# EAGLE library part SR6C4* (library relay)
Safety Relay SR6 SCHRACK sensitive 6 pole 8 A Source: http://www.schrack.com/.. 6688.pdf
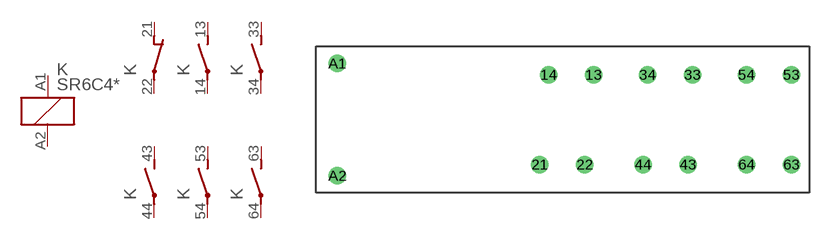
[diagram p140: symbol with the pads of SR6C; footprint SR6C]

Designator prefix K; gates 1=K 2=O 3=S 4=S 5=S 6=S 7=S

## SR6C4S05 (OC_FARNELL: unknown; OC_NEWARK: unknown), SR6C4S06 (OC_FARNELL: unknown; OC_NEWARK: unknown), SR6C4S09 (OC_FARNELL: unknown; OC_NEWARK: unknown), SR6C4S12 (OC_FARNELL: unknown; OC_NEWARK: unknown), SR6C4S15 (OC_FARNELL: unknown; OC_NEWARK: unknown), SR6C4S18 (OC_FARNELL: unknown; OC_NEWARK: unknown), SR6C4S21 (OC_FARNELL: unknown; OC_NEWARK: unknown), SR6C4S24 (OC_FARNELL: unknown; OC_NEWARK: unknown), SR6C4S36 (OC_FARNELL: unknown; OC_NEWARK: unknown), SR6C4S40 (OC_FARNELL: unknown; OC_NEWARK: unknown), SR6C4S48 (OC_FARNELL: unknown; OC_NEWARK: unknown)  [SR6C]
13  3:S  pas
14  3:P  pas
21  2:O  pas
22  2:P  pas
33  4:S  pas
34  4:P  pas
43  5:S  pas
44  5:P  pas
53  6:S  pas
54  6:P  pas
63  7:S  pas
64  7:P  pas
A1  1:1  pas
A2  1:2  pas

## Footprint SR6C (pad centres in mm)
Safety Relay SR6 SCHRACK sensitive 6 pole 8 A, Type C Source: http://www.schrack.com/.. 6688.pdf
drill 1.3 pad 1 round: 13 5.7,4.7; 14 0.7,4.7; 21 -0.3,-5.3; 22 4.7,-5.3; 33 16.7,4.7; 34 11.7,4.7; 43 16.2,-5.3; 44 11.2,-5.3; 53 27.7,4.7; 54 22.7,4.7; 63 27.7,-5.3; 64 22.7,-5.3; A1 -22.8,5.95; A2 -22.8,-6.55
